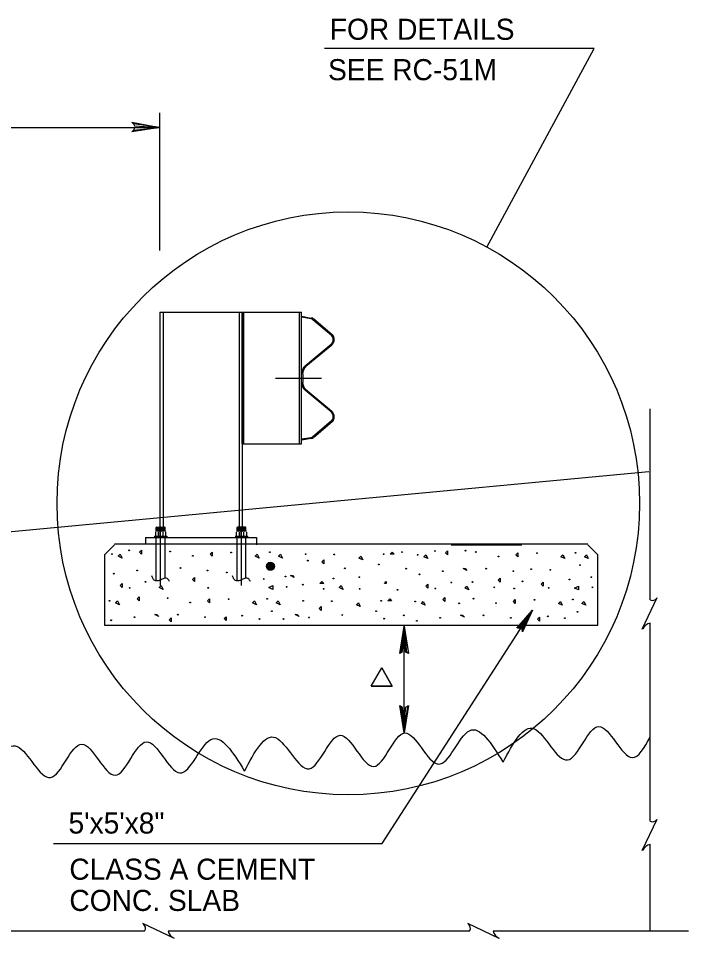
# Model space of a CAD drawing. Extents: x 639011 to 639866, y 298840 to 300028.
# Drawn here: x 639518 to 639613.5, y 298939.1 to 299070.1 of the extents above; entities that cross this region are included whole.
import ezdxf

# ---------------------------------------------------------------- set-up
doc = ezdxf.new("R2010")
doc.units = 0
doc.layers.add('2', color=7, linetype='Continuous')

msp = doc.modelspace()

# ---------------------------------------------------------------- linework, layer by layer
at = {"layer": '2'}
for p, q in [((639600.02, 299065.78), (639561.61, 299065.78)), ((639584.72, 299037.5), (639600.02, 299065.78)), ((639538.17, 299037.06), (639538.17, 299056.62)), ((639465.12, 299054.56), (639538.17, 299054.56)), ((639538.17, 299028.25), (639549.9, 299028.25)), ((639538.17, 299028.25), (639538.17, 298997.68)), ((639538.63, 299028.25), (639538.63, 298997.68)), ((639549.44, 299028.25), (639549.44, 298997.74)), ((639549.9, 299009.53), (639549.9, 299028.25)), ((639549.9, 299028.25), (639558.33, 299028.25)), ((639549.9, 299028.25), (639549.9, 298997.74)), ((639550.14, 299009.53), (639550.14, 299028.25)), ((639558.04, 299009.53), (639558.04, 299028.25)), ((639558.33, 299009.53), (639558.33, 299028.25)), ((639558.33, 299027.72), (639559.73, 299027.43)), ((639558.33, 299027.55), (639558.33, 299027.72)), ((639559.73, 299027.32), (639558.33, 299027.55)), ((639562.57, 299024.99), (639559.96, 299027.2)), ((639560.08, 299027.32), (639562.69, 299025.11)), ((639558.85, 299020.63), (639562.57, 299023.71)), ((639562.63, 299023.6), (639558.97, 299020.52)), ((639554.61, 299018.89), (639561.18, 299018.89)), ((639558.33, 299018.89), (639558.33, 299019.47)), ((639558.33, 299018.31), (639558.33, 299018.89)), ((639558.51, 299019.47), (639558.51, 299018.89)), ((639558.51, 299018.89), (639558.51, 299018.31)), ((639562.57, 299014.07), (639558.85, 299017.15)), ((639558.97, 299017.26), (639562.63, 299014.18)), ((639607.96, 298987.35), (639607.96, 299014.51)), ((639559.96, 299010.58), (639562.57, 299012.79)), ((639562.69, 299012.67), (639560.08, 299010.46)), ((639558.33, 299010.23), (639559.73, 299010.46)), ((639549.9, 299009.53), (639558.33, 299009.53)), ((639559.73, 299010.29), (639558.33, 299010.06)), ((639558.33, 299010.06), (639558.33, 299010.23)), ((639465.12, 298992.16), (639607.78, 299005.6)), ((639537.64, 298997.62), (639538.92, 298997.62)), ((639537.64, 298997.1), (639537.64, 298997.62)), ((639537.64, 298997.45), (639538.92, 298997.45)), ((639537.76, 298997.68), (639538.8, 298997.68)), ((639537.82, 298997.5), (639538.8, 298997.5)), ((639538.28, 298989.38), (639538.28, 298997.79)), ((639538.28, 298997.1), (639538.28, 298997.62)), ((639538.92, 298997.1), (639538.92, 298997.62)), ((639549.15, 298997.62), (639550.43, 298997.62)), ((639549.15, 298997.1), (639549.15, 298997.62)), ((639549.15, 298997.45), (639550.43, 298997.45)), ((639549.27, 298997.74), (639550.31, 298997.74)), ((639549.32, 298997.56), (639550.31, 298997.56)), ((639549.32, 298997.39), (639550.31, 298997.39)), ((639549.79, 298989.38), (639549.79, 298997.79)), ((639549.79, 298997.1), (639549.79, 298997.62)), ((639550.43, 298997.1), (639550.43, 298997.62)), ((639536.13, 298996.23), (639551.94, 298996.23)), ((639536.13, 298996.23), (639536.13, 298995.24)), ((639536.13, 298996.07), (639536.13, 298995.24)), ((639537.41, 298996.4), (639539.15, 298996.4)), ((639537.41, 298996.4), (639537.41, 298996.23)), ((639537.41, 298996.23), (639539.15, 298996.23)), ((639537.58, 298996.4), (639537.58, 298996.98)), ((639537.64, 298997.27), (639538.92, 298997.27)), ((639537.64, 298990.07), (639537.64, 298996.23)), ((639537.76, 298997.16), (639537.76, 298997.16)), ((639537.76, 298997.16), (639538.8, 298997.16)), ((639537.82, 298997.33), (639538.8, 298997.33)), ((639537.82, 298997.16), (639537.82, 298997.16)), ((639537.82, 298997.16), (639538.8, 298997.16)), ((639537.99, 298996.4), (639537.99, 298996.98)), ((639537.99, 298996.98), (639537.99, 298996.4)), ((639538.17, 298997.16), (639538.22, 298997.16)), ((639538.28, 298997.16), (639538.4, 298997.16)), ((639538.28, 298996.23), (639538.28, 298996.28)), ((639538.57, 298996.98), (639538.57, 298996.4)), ((639538.57, 298996.98), (639538.57, 298996.4)), ((639538.75, 298997.16), (639538.8, 298997.16)), ((639538.75, 298997.16), (639538.8, 298997.16)), ((639538.92, 298990.43), (639538.92, 298996.23)), ((639538.98, 298996.98), (639538.98, 298996.4)), ((639539.15, 298996.4), (639539.15, 298996.23)), ((639548.92, 298996.4), (639550.66, 298996.4)), ((639548.92, 298996.4), (639548.92, 298996.23)), ((639548.92, 298996.23), (639550.66, 298996.23)), ((639549.09, 298996.4), (639549.09, 298996.98)), ((639549.15, 298997.27), (639550.43, 298997.27)), ((639549.15, 298990.07), (639549.15, 298996.23)), ((639549.27, 298997.16), (639549.27, 298997.16)), ((639549.27, 298997.16), (639550.31, 298997.16)), ((639549.32, 298997.16), (639549.32, 298997.16)), ((639549.32, 298997.16), (639550.31, 298997.16)), ((639549.5, 298996.4), (639549.5, 298996.98)), ((639549.5, 298996.98), (639549.5, 298996.4)), ((639549.67, 298997.16), (639549.73, 298997.16)), ((639549.79, 298997.16), (639549.9, 298997.16)), ((639549.79, 298996.23), (639549.79, 298996.28)), ((639550.08, 298996.98), (639550.08, 298996.4)), ((639550.08, 298996.98), (639550.08, 298996.4)), ((639550.25, 298997.16), (639550.31, 298997.16)), ((639550.25, 298997.16), (639550.31, 298997.16)), ((639550.43, 298997.1), (639550.43, 298997.21)), ((639550.43, 298990.43), (639550.43, 298996.23)), ((639550.49, 298996.98), (639550.49, 298996.4)), ((639550.66, 298996.4), (639550.66, 298996.23)), ((639551.94, 298996.23), (639551.94, 298995.18)), ((639531.73, 298995.18), (639530.28, 298993.73)), ((639599.1, 298995.24), (639531.73, 298995.24)), ((639579.66, 298995.15), (639589.7, 298995.15)), ((639599.1, 298995.18), (639600.55, 298993.73)), ((639530.28, 298993.73), (639530.28, 298983.72)), ((639600.55, 298983.72), (639600.55, 298993.73)), ((639606.86, 298983.15), (639608.99, 298987.65)), ((639569.83, 298952.68), (639591.24, 298985.87)), ((639530.28, 298983.72), (639600.55, 298983.72)), ((639572.97, 298968.41), (639572.97, 298983.59)), ((639607.96, 298955.84), (639607.96, 298984.04)), ((639568.25, 298975.04), (639569.75, 298977.64)), ((639571.25, 298975.04), (639569.75, 298977.64)), ((639568.25, 298975.04), (639571.25, 298975.04)), ((639606.86, 298951.65), (639608.99, 298956.15)), ((639523.02, 298952.68), (639569.83, 298952.68)), ((639607.96, 298940.26), (639607.96, 298952.55)), ((639540.24, 298939.13), (639535.74, 298941.26)), ((639586.5, 298939.14), (639582, 298941.26)), ((639493.08, 298940.26), (639536.05, 298940.26)), ((639539.34, 298940.26), (639582.32, 298940.26)), ((639585.61, 298940.26), (639613.45, 298940.26))]:
    msp.add_line(p, q, dxfattribs=at)
for points in [[(639534.42, 299055.06), (639534.54, 299054.81), (639538.17, 299054.56), (639534.42, 299055.06), (639534.17, 299055.31), (639538.17, 299054.56), (639534.54, 299054.44), (639534.42, 299054.19), (639538.17, 299054.56), (639534.17, 299053.94), (639534.42, 299054.19)], [(639532.23, 298993.57), (639532.51, 298993.84), (639532.79, 298993.29), (639532.23, 298993.57)], [(639535.29, 298994.12), (639535.57, 298994.4), (639535.57, 298993.84), (639535.29, 298994.12)], [(639545.33, 298993.84), (639545.61, 298994.12), (639545.61, 298993.57), (639545.33, 298993.84)], [(639551.74, 298993.57), (639552.02, 298993.84), (639552.3, 298993.29), (639551.74, 298993.57)], [(639555.08, 298993.57), (639555.36, 298993.84), (639555.64, 298993.29), (639555.08, 298993.57)], [(639566.51, 298993.29), (639566.79, 298993.57), (639567.07, 298993.01), (639566.51, 298993.29)], [(639570.97, 298993.84), (639571.25, 298994.12), (639571.53, 298993.84), (639570.97, 298993.84)], [(639575.76, 298993.47), (639576.04, 298993.75), (639576.32, 298993.2), (639575.76, 298993.47)], [(639578.83, 298994.03), (639579.11, 298994.31), (639579.11, 298993.75), (639578.83, 298994.03)], [(639588.86, 298993.75), (639589.14, 298994.03), (639589.14, 298993.47), (639588.86, 298993.75)], [(639595.27, 298993.47), (639595.55, 298993.75), (639595.83, 298993.2), (639595.27, 298993.47)], [(639598.62, 298993.47), (639598.9, 298993.75), (639599.17, 298993.2), (639598.62, 298993.47)], [(639561.21, 298992.73), (639561.49, 298993.01), (639561.49, 298992.45), (639561.21, 298992.73)], [(639581.34, 298991.8), (639581.62, 298991.8), (639581.89, 298991.52), (639581.34, 298991.8)], [(639532.51, 298989.38), (639532.79, 298989.66), (639532.79, 298989.11), (639532.51, 298989.38)], [(639542.82, 298990.22), (639543.1, 298990.5), (639543.1, 298989.94), (639542.82, 298990.22)], [(639556.76, 298990.78), (639557.03, 298990.78), (639557.31, 298990.5), (639556.76, 298990.78)], [(639560.94, 298989.66), (639561.21, 298989.94), (639561.49, 298989.66), (639560.94, 298989.66)], [(639570.13, 298989.66), (639570.41, 298989.94), (639570.41, 298989.66), (639570.13, 298989.66)], [(639576.04, 298989.29), (639576.32, 298989.57), (639576.32, 298989.01), (639576.04, 298989.29)], [(639586.35, 298990.13), (639586.63, 298990.41), (639586.63, 298989.85), (639586.35, 298990.13)], [(639592.48, 298989.57), (639592.76, 298989.85), (639592.76, 298989.29), (639592.48, 298989.57)], [(639538.08, 298989.11), (639538.36, 298989.38), (639538.64, 298988.83), (639538.08, 298989.11)], [(639553.69, 298989.11), (639554.25, 298989.38), (639554.25, 298988.83), (639553.69, 298989.11)], [(639563.72, 298989.11), (639564, 298989.38), (639564.28, 298988.83), (639563.72, 298989.11)], [(639581.62, 298989.01), (639581.89, 298989.29), (639582.17, 298988.74), (639581.62, 298989.01)], [(639597.22, 298989.01), (639597.78, 298989.29), (639597.78, 298988.74), (639597.22, 298989.01)], [(639531.87, 298986.93), (639532.14, 298987.21), (639532.42, 298986.65), (639531.87, 298986.93)], [(639534.93, 298987.49), (639535.21, 298987.77), (639535.21, 298987.21), (639534.93, 298987.49)], [(639544.96, 298987.21), (639545.24, 298987.49), (639545.24, 298986.93), (639544.96, 298987.21)], [(639551.38, 298986.93), (639551.65, 298987.21), (639551.93, 298986.65), (639551.38, 298986.93)], [(639554.72, 298986.93), (639555, 298987.21), (639555.28, 298986.65), (639554.72, 298986.93)], [(639566.15, 298986.65), (639566.43, 298986.93), (639566.7, 298986.37), (639566.15, 298986.65)], [(639570.61, 298987.21), (639570.89, 298987.49), (639571.16, 298987.21), (639570.61, 298987.21)], [(639575.4, 298986.84), (639575.68, 298987.12), (639575.96, 298986.56), (639575.4, 298986.84)], [(639578.46, 298987.4), (639578.74, 298987.68), (639578.74, 298987.12), (639578.46, 298987.4)], [(639588.5, 298987.12), (639588.78, 298987.4), (639588.78, 298986.84), (639588.5, 298987.12)], [(639594.91, 298986.84), (639595.19, 298987.12), (639595.47, 298986.56), (639594.91, 298986.84)], [(639598.25, 298986.84), (639598.53, 298987.12), (639598.81, 298986.56), (639598.25, 298986.84)], [(639560.85, 298986.09), (639561.13, 298986.37), (639561.13, 298985.82), (639560.85, 298986.09)], [(639589.15, 298983.35), (639589.43, 298983.32), (639591.24, 298985.87), (639589.15, 298983.35), (639588.98, 298983.32), (639591.24, 298985.87), (639589.64, 298983.18), (639589.78, 298982.94), (639591.24, 298985.87), (639589.82, 298982.77), (639589.78, 298982.94)], [(639537.44, 298985.26), (639537.72, 298985.26), (639538, 298984.98), (639537.44, 298985.26)], [(639539.51, 298984.48), (639539.79, 298984.76), (639539.79, 298984.2), (639539.51, 298984.48)], [(639547.33, 298984.66), (639547.61, 298984.94), (639547.61, 298984.39), (639547.33, 298984.66)], [(639557.42, 298985.24), (639557.7, 298985.24), (639557.98, 298984.96), (639557.42, 298985.24)], [(639580.97, 298985.17), (639581.25, 298985.17), (639581.53, 298984.89), (639580.97, 298985.17)], [(639591.95, 298984.57), (639592.23, 298984.85), (639592.23, 298984.29), (639591.95, 298984.57)], [(639572.47, 298979.84), (639572.72, 298979.97), (639572.97, 298983.59), (639572.47, 298979.84), (639572.34, 298979.72), (639572.97, 298983.59), (639573.09, 298979.97), (639573.34, 298979.84), (639572.97, 298983.59), (639573.59, 298979.72), (639573.34, 298979.84)], [(639573.47, 298972.16), (639573.09, 298972.03), (639572.97, 298968.41), (639573.47, 298972.16), (639573.59, 298972.28), (639572.97, 298968.41), (639572.72, 298972.03), (639572.47, 298972.16), (639572.97, 298968.41), (639572.34, 298972.28), (639572.47, 298972.16)]]:
    msp.add_lwpolyline(points, dxfattribs=at)
msp.add_lwpolyline([(639568.25, 298975.04), (639569.75, 298977.64), (639571.25, 298975.04), (639568.25, 298975.04)], close=True, dxfattribs=at)
for centre, radius in [((639565, 299001.07), 41.47), ((639531.35, 298993.83), 0.0561), ((639533.81, 298994.38), 0.0561), ((639539.64, 298994.23), 0.0561), ((639542.85, 298993.6), 0.0561), ((639548.33, 298994.08), 0.0561), ((639553.81, 298994.13), 0.0561), ((639558.93, 298993.83), 0.0561), ((639563, 298993.78), 0.0561), ((639570.04, 298993.83), 0.0561), ((639572.65, 298994.13), 0.0561), ((639574.88, 298993.73), 0.0561), ((639577.34, 298994.29), 0.0561), ((639581.67, 298994.34), 0.0561), ((639583.17, 298994.14), 0.0561), ((639586.39, 298993.51), 0.0561), ((639591.86, 298993.99), 0.0561), ((639597.34, 298994.04), 0.0561), ((639553.91, 298992.11), 0.572), ((639553.91, 298992.11), 0.531), ((639553.91, 298992.11), 0.491), ((639553.91, 298992.11), 0.45), ((639553.91, 298992.11), 0.409), ((639553.91, 298992.11), 0.369), ((639553.91, 298992.11), 0.328), ((639553.91, 298992.11), 0.288), ((639553.91, 298992.11), 0.247), ((639553.91, 298992.11), 0.206), ((639553.91, 298992.11), 0.166), ((639553.91, 298992.11), 0.125), ((639553.91, 298992.11), 0.0845), ((639553.91, 298992.11), 0.0439), ((639559.23, 298992.92), 0.0561), ((639569.33, 298992.37), 0.0561), ((639597.99, 298992.28), 0.0561), ((639531.6, 298991.06), 0.0561), ((639534.92, 298991.51), 0.0561), ((639541.1, 298991.87), 0.0561), ((639544.96, 298991.51), 0.0561), ((639547.7, 298991.23), 0.0561), ((639564.51, 298991.82), 0.0561), ((639573.25, 298991.77), 0.0561), ((639575.13, 298990.97), 0.0561), ((639578.45, 298991.42), 0.0561), ((639584.63, 298991.78), 0.0561), ((639588.5, 298991.42), 0.0561), ((639591.03, 298991.69), 0.0561), ((639593.77, 298991.62), 0.0561), ((639536.12, 298989.91), 0.0561), ((639552.95, 298990.31), 0.0561), ((639556.07, 298990.66), 0.0561), ((639558.53, 298989.5), 0.0561), ((639562.9, 298990.36), 0.0561), ((639566.57, 298990.56), 0.0561), ((639579.66, 298989.82), 0.0561), ((639582.67, 298989.87), 0.0561), ((639589.8, 298989.97), 0.0561), ((639596.49, 298990.22), 0.0561), ((639599.6, 298990.57), 0.0561), ((639533.86, 298989.05), 0.0561), ((639545.06, 298989.05), 0.0561), ((639556.22, 298989.2), 0.0561), ((639561.49, 298988.9), 0.0561), ((639566.62, 298988.9), 0.0561), ((639571.99, 298988.75), 0.0561), ((639577.39, 298988.96), 0.0561), ((639585.79, 298989.11), 0.0561), ((639588.6, 298988.96), 0.0561), ((639593.52, 298989.06), 0.0561), ((639599.75, 298989.11), 0.0561), ((639530.99, 298987.19), 0.0561), ((639539.28, 298987.59), 0.0561), ((639542.49, 298986.97), 0.0561), ((639547.97, 298987.44), 0.0561), ((639553.44, 298987.49), 0.0561), ((639558.57, 298987.19), 0.0561), ((639562.64, 298987.14), 0.0561), ((639569.67, 298987.19), 0.0561), ((639574.52, 298987.1), 0.0561), ((639580.79, 298986.84), 0.0561), ((639582.81, 298987.5), 0.0561), ((639586.02, 298986.87), 0.0561), ((639591.5, 298987.35), 0.0561), ((639596.97, 298987.4), 0.0561), ((639554.1, 298985.73), 0.0561), ((639568.97, 298985.73), 0.0561), ((639597.63, 298985.64), 0.0561), ((639531.24, 298984.43), 0.0561), ((639534.55, 298984.88), 0.0561), ((639540.73, 298985.23), 0.0561), ((639544.6, 298984.88), 0.0561), ((639549.88, 298985.08), 0.0561), ((639552.35, 298984.61), 0.0561), ((639555.77, 298984.61), 0.0561), ((639559.4, 298984.84), 0.0561), ((639564.14, 298985.18), 0.0561), ((639570.09, 298984.66), 0.0561), ((639572.89, 298985.13), 0.0561), ((639574.77, 298984.34), 0.0561), ((639578.09, 298984.79), 0.0561), ((639584.26, 298985.14), 0.0561), ((639588.13, 298984.79), 0.0561), ((639593.41, 298984.99), 0.0561), ((639595.83, 298984.73), 0.0561)]:
    msp.add_circle(centre, radius, dxfattribs=at)
for centre, radius, start, end in [((639559.61, 299026.78), 0.539, 50.0087, 79.9673), ((639559.62, 299026.78), 0.69, 50, 79.9701), ((639561.99, 299024.37), 0.864, 310.9606, 46.6292), ((639561.99, 299024.37), 1.01, 310.9606, 46.6292), ((639559.83, 299019.47), 1.5, 130.0127, 180), ((639559.83, 299019.47), 1.35, 130.0127, 180), ((639559.83, 299018.3), 1.5, 180, 229.9873), ((639559.83, 299018.3), 1.35, 180, 229.9873), ((639561.99, 299013.4), 0.864, 313.3708, 49.0394), ((639561.99, 299013.4), 1.01, 313.3708, 49.0394), ((639559.61, 299010.98), 0.539, 280.0327, 309.9913), ((639559.62, 299010.99), 0.69, 280.0299, 310), ((639537.9, 298997.44), 0.3, 120.6813, 145.7389), ((639537.9, 298997.44), 0.3, 120.6813, 145.7389), ((639538.66, 298997.44), 0.3, 34.2611, 59.3187), ((639549.41, 298997.47), 0.3, 120.6813, 145.7389), ((639549.41, 298997.47), 0.3, 120.6813, 145.7389), ((639550.17, 298997.47), 0.3, 34.2611, 59.3187), ((639608.31, 298988.03), 0.767, 245.2452, 323.2548), ((639608.31, 298956.53), 0.767, 245.2452, 323.2548), ((639535.36, 298940.59), 0.767, 335.2452, 53.2548), ((639581.62, 298940.59), 0.767, 335.2452, 53.2548)]:
    msp.add_arc(centre, radius, start, end, dxfattribs=at)
for centre, major_axis, ratio, start_param, end_param in [((639537.74, 298997), (-0.18, 0), 0.8, 4.712389, 6.283185), ((639537.83, 298997), (-0.18, 0), 0.8, 3.141593, 4.712389), ((639538.19, 298997), (-0.18, 0), 0.8, 4.712389, 6.283185), ((639538.37, 298997), (0.18, 0), 0.8, 0, 1.570796), ((639538.73, 298997), (-0.18, 0), 0.8, 4.712389, 6.283185), ((639538.82, 298997), (0.18, 0), 0.8, 0, 1.570796), ((639549.25, 298997), (-0.18, 0), 0.8, 4.712389, 6.283185), ((639549.34, 298997), (-0.18, 0), 0.8, 3.141593, 4.712389), ((639549.7, 298997), (-0.18, 0), 0.8, 4.712389, 6.283185), ((639549.88, 298997), (0.18, 0), 0.8, 0, 1.570796), ((639550.24, 298997), (-0.18, 0), 0.8, 4.712389, 6.283185), ((639550.33, 298997), (0.18, 0), 0.8, 0, 1.570796), ((639608.27, 298982.27), (-0.3, 1.77), 0.84059, 0.001606, 0.896554), ((639608.27, 298950.77), (-0.3, 1.77), 0.84059, 0.001606, 0.896554), ((639541.12, 298940.54), (-1.77, -0.3), 0.84059, 0.001606, 0.896554), ((639587.38, 298940.54), (-1.77, -0.3), 0.84059, 0.001606, 0.896554)]:
    msp.add_ellipse(centre, major_axis=major_axis, ratio=ratio, start_param=start_param, end_param=end_param, dxfattribs=at)
for points in [[(639539.56, 298989.93), (639539.32, 298990.28), (639538.74, 298990.39), (639538.28, 298990.16), (639537.81, 298990.04), (639537.35, 298990.16), (639537.11, 298990.51), (639537, 298990.74)], [(639551.05, 298989.93), (639550.82, 298990.28), (639550.24, 298990.39), (639549.77, 298990.16), (639549.31, 298990.04), (639548.84, 298990.16), (639548.61, 298990.51), (639548.5, 298990.74)], [(639550.22, 298962.97), (639554.65, 298967.73), (639559.42, 298963.3), (639563.85, 298968.06), (639568.61, 298963.63), (639573.04, 298968.39), (639577.8, 298963.96), (639582.24, 298968.72), (639587, 298964.29)], [(639587.03, 298964.22), (639591.46, 298968.99), (639596.22, 298964.55), (639600.66, 298969.31), (639605.42, 298964.88), (639607.96, 298967.79)], [(639513.41, 298961.72), (639517.85, 298966.48), (639522.61, 298962.05), (639527.04, 298966.81), (639531.8, 298962.38), (639536.24, 298967.14), (639541, 298962.71), (639545.43, 298967.47), (639550.19, 298963.03)]]:
    msp.add_spline(points, degree=3, dxfattribs=at)

# ---------------------------------------------------------------- texts
for s, p in [('FOR DETAILS', (639562.36, 299067.03)), ('SEE RC-51M', (639562.11, 299061.28)), ('5\'x5\'x8"', (639525.16, 298954.08)), ('CLASS A CEMENT', (639525.28, 298947.51)), ('CONC. SLAB', (639525.28, 298943.07))]:
    msp.add_text(s, height=3, dxfattribs=at).set_placement(p)

doc.saveas('drawing.dxf')
